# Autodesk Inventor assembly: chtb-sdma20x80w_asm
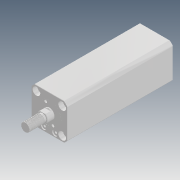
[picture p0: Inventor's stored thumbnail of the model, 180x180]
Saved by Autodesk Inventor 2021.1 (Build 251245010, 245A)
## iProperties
Company: Microsoft
Created: 2018-05
Part Number: chtb-sdma20x80w_asm
Description: STEP AP214
Document SubType Name: Assembly
Designer: user
Title: chtb-sdma20x80w_asm.STEP
Author: Windows
Revision Number: ÈÎºÎ
Sending System: SolidWorks 2015
Preprocessor: SwSTEP 2.0
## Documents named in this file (4)
- D:\Vault_2016\Projekty\Clamptek\Hydraulic\CHTB\CHTB-20\Inventor\CHTB-SDMA20x80W\chtb-sdma20x80w_asm.iam
- D:\Vault_2016\Projekty\Clamptek\Hydraulic\CHTB\CHTB-20\Inventor\CHTB-SDMA20x80W\CHTB-SDMA20X80NBT.ipt
- D:\Vault_2016\Projekty\Clamptek\Hydraulic\CHTB\CHTB-20\Inventor\CHTB-SDMA20x80W\CHTB-SDMA20X80WHSG.ipt
- D:\Vault_2016\Projekty\Clamptek\Hydraulic\CHTB\CHTB-20\Inventor\CHTB-SDMA20x80W\QG_3.ipt
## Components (3 placed, 3 different names)
1. CHTB-SDMA20X80NBT_1
2. CHTB-SDMA20X80WHSG_2
3. QG_3_3
